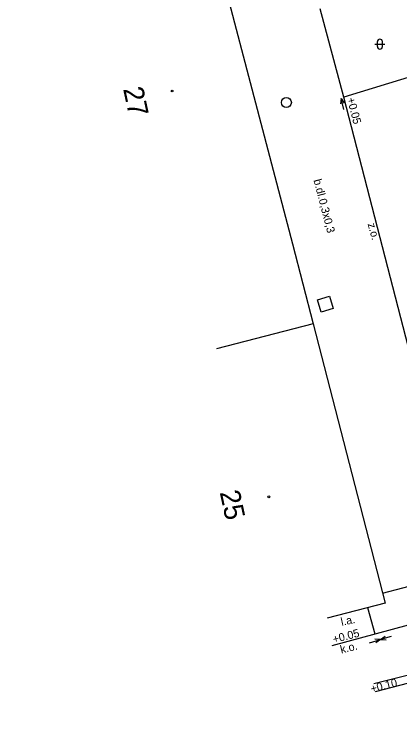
# Model space of a CAD drawing. Extents: x -598577 to -598446, y -1159390 to -1159053.
# Drawn here: x -598527.02 to -598507.79, y -1159307.3 to -1159271.08 of the extents above; entities that cross this region are included whole.
import ezdxf

# ---------------------------------------------------------------- set-up
doc = ezdxf.new("R2010")
doc.units = 0
for name, color, linetype in [('Vrstva 14', 7, 'Continuous'), ('Vrstva 15', 7, 'Continuous'), ('Vrstva 23', 7, 'Continuous'), ('Vrstva 25', 7, 'Continuous'), ('Vrstva 4', 7, 'Continuous'), ('Vrstva 43', 7, 'Continuous'), ('Vrstva 49', 7, 'Continuous'), ('Vrstva 50', 7, 'Continuous'), ('Vrstva 7', 7, 'Continuous')]:
    doc.layers.add(name, color=color, linetype=linetype)

msp = doc.modelspace()

# ---------------------------------------------------------------- linework, layer by layer
at = {"layer": 'Vrstva 14'}
for p, q in [((-598509.017, -1159272.564), (-598508.517, -1159272.564)), ((-598508.892, -1159272.689), (-598508.892, -1159272.439)), ((-598508.642, -1159272.689), (-598508.642, -1159272.439))]:
    msp.add_line(p, q, dxfattribs=at)
for centre, start, end in [((-598508.767, -1159272.439), 0, 180), ((-598508.767, -1159272.689), 180, 360)]:
    msp.add_arc(centre, 0.125, start, end, dxfattribs=at)
at = {"layer": 'Vrstva 15'}
for centre in [(-598519.149, -1159274.904), (-598514.315, -1159295.173)]:
    msp.add_circle(centre, 0.0438, dxfattribs=at)
at = {"layer": 'Vrstva 23'}
msp.add_lwpolyline([(-598511.88, -1159285.34), (-598511.28, -1159285.16), (-598511.098, -1159285.768), (-598511.698, -1159285.948)], close=True, dxfattribs=at)
at = {"layer": 'Vrstva 25'}
msp.add_circle((-598513.44, -1159275.48), 0.25, dxfattribs=at)
at = {"layer": 'Vrstva 4'}
msp.add_line((-598512.095, -1159286.536), (-598516.936, -1159287.787), dxfattribs=at)
for points in [[(-598527.02, -1159249.7), (-598522.1, -1159248.44), (-598518.42, -1159262.41), (-598513.13, -1159282.53), (-598512.095, -1159286.536), (-598508.51, -1159300.48), (-598511.41, -1159301.23)], [(-598508.637, -1159299.987), (-598505.59, -1159299.19), (-598504.39, -1159303.71)], [(-598502.82, -1159309.87), (-598504.39, -1159303.71), (-598509.01, -1159304.91)]]:
    msp.add_lwpolyline(points, dxfattribs=at)
at = {"layer": 'Vrstva 49'}
for p, q in [((-598510.704, -1159275.271), (-598510.735, -1159275.552)), ((-598510.575, -1159275.82), (-598510.704, -1159275.271)), ((-598510.704, -1159275.271), (-598510.549, -1159275.506)), ((-598509.281, -1159302.462), (-598508.739, -1159302.305)), ((-598508.739, -1159302.305), (-598509.022, -1159302.288)), ((-598508.739, -1159302.305), (-598508.966, -1159302.472)), ((-598508.74, -1159302.305), (-598508.513, -1159302.137)), ((-598508.198, -1159302.147), (-598508.739, -1159302.305)), ((-598508.739, -1159302.305), (-598508.457, -1159302.321))]:
    msp.add_line(p, q, dxfattribs=at)
at = {"layer": 'Vrstva 7'}
for points in [[(-598510.57, -1159275.21), (-598511.75, -1159270.8)], [(-598506.918, -1159274.104), (-598510.57, -1159275.21)], [(-598504.33, -1159299.17), (-598507.18, -1159288.23), (-598506.56, -1159288.07), (-598506.7, -1159287.55), (-598507.34, -1159287.71), (-598510.57, -1159275.21)], [(-598511.15, -1159302.6), (-598505.118, -1159300.968)], [(-598509.38, -1159300.705), (-598509.013, -1159302.022)], [(-598509.07, -1159304.5), (-598504.488, -1159303.342)]]:
    msp.add_lwpolyline(points, dxfattribs=at)

# ---------------------------------------------------------------- texts
at = {"layer": 'Vrstva 43'}
for s, p in [('27', (-598521.598, -1159274.799)), ('25', (-598516.773, -1159294.947))]:
    msp.add_text(s, height=1, rotation=282.2417, dxfattribs=at).set_placement(p)
at = {"layer": 'Vrstva 49'}
for s, rotation, p in [('b.dl.0,3x0,3', 284.6482, (-598512.087, -1159279.355)), ('z.o.', 285.6121, (-598509.384, -1159281.553)), ('l.a.', 12.4486, (-598510.674, -1159301.623)), ('k.o.', 14.2403, (-598510.693, -1159303.006))]:
    msp.add_text(s, height=0.4, rotation=rotation, dxfattribs=at).set_placement(p)
at = {"layer": 'Vrstva 50'}
for s, rotation, p in [('+0.05', 284.4883, (-598510.415, -1159275.283)), ('+0.05', 14.611, (-598511.07, -1159302.492)), ('+0.10', 14.611, (-598509.179, -1159304.968))]:
    msp.add_text(s, height=0.4, rotation=rotation, dxfattribs=at).set_placement(p)

doc.saveas('drawing.dxf')
